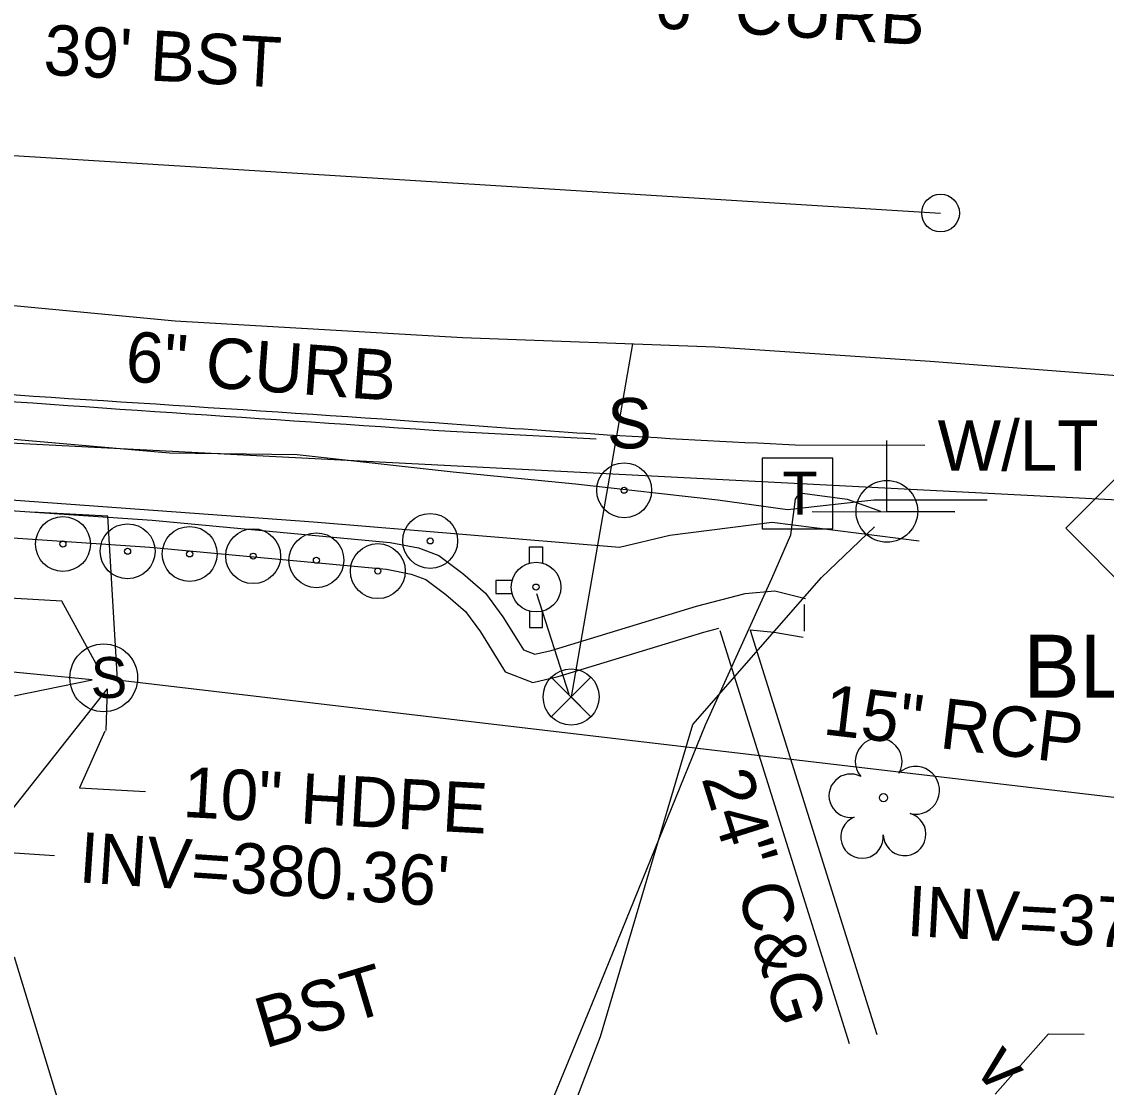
# Model space of a CAD drawing. Extents: x 2089016 to 2094354, y 862840 to 864725.
# Drawn here: x 2092984 to 2093070.2, y 863542.1 to 863626.7 of the extents above; entities that cross this region are included whole.
import ezdxf

# ---------------------------------------------------------------- set-up
doc = ezdxf.new("R2010")
doc.units = 0
for name, color, linetype in [('CTL Supplemental Horizontal and Vertical CELL', 7, 'Continuous'), ('CTL Supplemental Horizontal and Vertical Text', 7, 'Continuous'), ('Exist Building', 7, 'Continuous'), ('Exist Horizontal Alignment', 7, 'Continuous'), ('Exist Horizontal Alignment Station Label', 7, 'Continuous'), ('Exist Other Culture Located Object CELL', 7, 'Continuous'), ('Exist Other Culture Sign Text', 7, 'Continuous'), ('Exist Right of Way Line', 7, 'Continuous'), ('Exist Roads Curbs', 7, 'Continuous'), ('Exist Roads Curbs Text', 7, 'Continuous'), ('Exist Roads EOP', 7, 'Continuous'), ('Exist Roads EOP Other', 7, 'Continuous'), ('Exist Roads EOP Other Text', 7, 'Continuous'), ('Exist Roads EOP Text', 7, 'Continuous'), ('Exist Structure Minor Culvert Topo Terminator', 7, 'Continuous'), ('Exist Structure Minor Paved Ditch or Gutter', 7, 'Continuous'), ('Exist Structure Minor Pipes HDPE 10 Inch', 7, 'Continuous'), ('Exist Structure Minor Pipes HDPE 10 Inch Invert', 7, 'Continuous'), ('Exist Structure Minor Pipes HDPE 10 Inch Leader', 7, 'Continuous'), ('Exist Structure Minor Pipes HDPE 10 Inch Text', 7, 'Continuous'), ('Exist Structure Minor Pipes RCP 15 Inch', 7, 'Continuous'), ('Exist Structure Minor Pipes RCP 15 Inch Invert', 7, 'Continuous'), ('Exist Structure Minor Pipes RCP 15 Inch Leader', 7, 'Continuous'), ('Exist Structure Minor Pipes RCP 15 Inch Text', 7, 'Continuous'), ('Exist Structure Minor Storm Sewer Manhole CELL', 7, 'Continuous'), ('Exist Structure Minor Storm Sewer Manhole Leader', 7, 'Continuous'), ('Exist Utilities Power Joint Use Telephone Text', 7, 'Continuous'), ('Exist Utilities Power UG Cable SUE LOS B', 7, 'Continuous'), ('Exist Utilities Telephone Pedestal CELL', 7, 'Continuous'), ('Exist Utilities Telephone UG Cable SUE LOS B', 7, 'Continuous'), ('Exist Utilities Water UG Line SUE LOS B', 7, 'Continuous'), ('Exist Utilities Water UG Line SUE LOS C', 7, 'Continuous'), ('Exist Vegetation Hedge Row', 7, 'Continuous'), ('Exist Vegetation Tree CELL', 7, 'Continuous'), ('Prop Conc Driveway', 7, 'Continuous'), ('Prop Erosion Embankment Toe Protection with Rip Rap 2 Detail CELL', 7, 'Continuous'), ('Prop Erosion Rip Rap Pad at Outlet Label', 7, 'Continuous'), ('Prop SS Fill Line', 7, 'Continuous'), ('R5707_NCDOT_FS_170814 - Exist Utilities Water UG Line SUE LOS B', 7, 'Continuous')]:
    doc.layers.add(name, color=color, linetype=linetype)

msp = doc.modelspace()

# ---------------------------------------------------------------- linework, layer by layer
at = {"layer": 'CTL Supplemental Horizontal and Vertical CELL'}
msp.add_lwpolyline([(2093067.004, 863586.524), (2093072.246, 863591.765), (2093077.496, 863586.515), (2093072.254, 863581.273)], close=True, dxfattribs=at)
at = {"layer": 'Exist Building'}
for p, q in [((2092978.975, 863589.073), (2093007.222, 863587.021)), ((2093007.222, 863587.021), (2093031.526, 863585.014))]:
    msp.add_line(p, q, dxfattribs=at)
msp.add_lwpolyline([(2092876.627, 863421.444), (2092852.192, 863498.242), (2092850.753, 863503.41), (2092851.048, 863506.429), (2092852.03, 863509.247), (2092853.537, 863511.694), (2092856.63, 863514.147), (2092866.579, 863516.845), (2092929.743, 863535.832), (2092983.435, 863552.499), (2093001.362, 863493.669), (2093002.398, 863490.352), (2093002.956, 863488.108), (2092994.326, 863472.797), (2093011.701, 863463.03), (2093003.046, 863446.38), (2092985.186, 863455.795), (2092876.596, 863421.423)], close=True, dxfattribs=at)
at = {"layer": 'Exist Horizontal Alignment'}
msp.add_line((2092859.181, 863623.858), (2093057.049, 863611.554), dxfattribs=at)
at = {"layer": 'Exist Horizontal Alignment Station Label'}
msp.add_circle((2093057.049, 863611.554), 1.5, dxfattribs=at)
at = {"layer": 'Exist Other Culture Located Object CELL'}
for centre, radius in [((2092987.318, 863585.27), 2.18), ((2092992.454, 863584.695), 2.18), ((2092997.385, 863584.482), 2.18), ((2093002.432, 863584.308), 2.18), ((2093007.458, 863583.983), 2.18), ((2092987.318, 863585.27), 0.24), ((2092992.454, 863584.695), 0.24), ((2093012.336, 863583.119), 2.18), ((2092997.385, 863584.482), 0.24), ((2093002.432, 863584.308), 0.24), ((2093007.458, 863583.983), 0.24), ((2093012.336, 863583.119), 0.24)]:
    msp.add_circle(centre, radius, dxfattribs=at)
at = {"layer": 'Exist Right of Way Line'}
msp.add_line((2092887.594, 863598.226), (2093123.991, 863586.06), dxfattribs=at)
at = {"layer": 'Exist Roads Curbs'}
msp.add_line((2093018.111, 863594.221), (2093029.677, 863593.627), dxfattribs=at)
for points in [[(2092894.675, 863574.886), (2092912.072, 863580.374), (2092930.578, 863586.234), (2092943.261, 863590.055), (2092945.833, 863590.454), (2092965.978, 863589.091), (2092994.403, 863587.166), (2093013.319, 863585.386), (2093015.572, 863584.956), (2093017.173, 863584.359), (2093019.088, 863582.941), (2093020.9, 863581.362), (2093022.271, 863579.494), (2093023.387, 863577.707), (2093023.897, 863576.857), (2093024.803, 863576.51), (2093026.116, 863576.811), (2093037.656, 863580.342), (2093041.515, 863581.328), (2093043.892, 863581.551), (2093046.328, 863580.947)], [(2093046.132, 863577.847), (2093043.825, 863578.232), (2093041.931, 863578.418), (2093045.789, 863566.093), (2093051.996, 863546.313)]]:
    msp.add_lwpolyline(points, dxfattribs=at)
msp.add_spline([(2092836.882, 863591.974), (2092839.402, 863592.978), (2092859.829, 863600.59), (2092883.194, 863603.249), (2092901.658, 863602.034), (2092935.152, 863599.946), (2092973.876, 863597.253), (2093018.111, 863594.221)], degree=3, dxfattribs=at)
at = {"layer": 'Exist Roads EOP'}
msp.add_line((2093045.487, 863593.143), (2093055.8, 863593.112), dxfattribs=at)
msp.add_spline([(2092783.649, 863530.803), (2092785.597, 863535.097), (2092792.694, 863549.723), (2092807.464, 863570.012), (2092820.61, 863582.257), (2092829.779, 863588.664), (2092831.761, 863589.721), (2092836.762, 863592.495), (2092839.093, 863593.515), (2092859.841, 863601.083), (2092883.166, 863603.689), (2092901.828, 863602.719), (2092935.142, 863600.426), (2092973.9, 863597.741), (2093018.255, 863594.812), (2093029.571, 863594.017), (2093045.487, 863593.143)], degree=3, dxfattribs=at)
at = {"layer": 'Exist Roads EOP Other'}
for points in [[(2092895.077, 863572.767), (2092912.717, 863578.332), (2092931.21, 863584.188), (2092943.736, 863587.961), (2092945.927, 863588.301), (2092965.833, 863586.955), (2092994.23, 863585.031), (2093013.018, 863583.263), (2093014.993, 863582.887), (2093016.141, 863582.458), (2093017.745, 863581.271), (2093019.314, 863579.903), (2093020.497, 863578.291), (2093021.56, 863576.588), (2093022.441, 863575.122), (2093024.645, 863574.277), (2093026.669, 863574.741), (2093038.235, 863578.28), (2093039.438, 863578.587)], [(2093039.507, 863578.399), (2093043.577, 863565.399), (2093049.783, 863545.619)]]:
    msp.add_lwpolyline(points, dxfattribs=at)
at = {"layer": 'Exist Structure Minor Paved Ditch or Gutter'}
msp.add_line((2093046.207, 863580.462), (2093046.215, 863578.34), dxfattribs=at)
at = {"layer": 'Exist Structure Minor Pipes HDPE 10 Inch'}
msp.add_line((2092990.823, 863573.765), (2092990.715, 863570.468), dxfattribs=at)
at = {"layer": 'Exist Structure Minor Pipes HDPE 10 Inch Leader'}
for points in [[(2092990.823, 863573.765), (2092980.658, 863560.937), (2092986.645, 863560.54)], [(2092990.644, 863570.398), (2092988.633, 863565.919), (2092993.868, 863565.629)]]:
    msp.add_lwpolyline(points, dxfattribs=at)
at = {"layer": 'Exist Structure Minor Pipes RCP 15 Inch'}
for p, q in [((2092856.706, 863547.53), (2092989.64, 863574.49)), ((2092991.647, 863574.488), (2093086.405, 863563.337))]:
    msp.add_line(p, q, dxfattribs=at)
at = {"layer": 'Exist Structure Minor Pipes RCP 15 Inch Leader'}
for points in [[(2092991.647, 863574.488), (2092990.888, 863587.476), (2092984.842, 863587.81)], [(2092989.64, 863574.49), (2092980.884, 863575.334), (2092974.894, 863575.665)], [(2093061.382, 863541.592), (2093065.634, 863546.385), (2093068.457, 863546.342)]]:
    msp.add_lwpolyline(points, dxfattribs=at)
at = {"layer": 'Exist Structure Minor Storm Sewer Manhole CELL'}
msp.add_circle((2092990.559, 863574.647), 2.694, dxfattribs=at)
at = {"layer": 'Exist Structure Minor Storm Sewer Manhole Leader'}
msp.add_lwpolyline([(2092990.559, 863574.647), (2092987.217, 863580.742), (2092981.226, 863581.073)], dxfattribs=at)
at = {"layer": 'Exist Utilities Power UG Cable SUE LOS B'}
msp.add_lwpolyline([(2093015.514, 863511.335), (2093023.641, 863529.45), (2093030.032, 863546.152), (2093037.352, 863570.951), (2093047.582, 863582.622), (2093051.807, 863586.63)], dxfattribs=at)
at = {"layer": 'Exist Utilities Telephone Pedestal CELL'}
msp.add_line((2093045.606, 863589.315), (2093045.606, 863589.315), dxfattribs=at)
msp.add_lwpolyline([(2093042.882, 863586.489), (2093048.476, 863586.489), (2093048.476, 863592.083), (2093042.882, 863592.083), (2093042.882, 863586.489)], dxfattribs=at)
at = {"layer": 'Exist Utilities Telephone UG Cable SUE LOS B'}
for points in [[(2092779.886, 863512.858), (2092788.107, 863530.526), (2092797.403, 863547.579), (2092809.235, 863563.23), (2092822.643, 863575.422), (2092828.878, 863582.856), (2092836.045, 863587.143), (2092845.526, 863592.531), (2092859.167, 863597.48), (2092876.604, 863599.467), (2092893.555, 863598.148), (2092906.053, 863598.419), (2092920.812, 863597.716), (2092953.006, 863595.424), (2092975.528, 863594.29), (2092995.787, 863592.5), (2093005.921, 863592.377), (2093018.315, 863590.993), (2093028.039, 863590.053), (2093039.357, 863588.772), (2093044.888, 863588.007), (2093051.758, 863588.783), (2093060.741, 863588.782)], [(2093017.627, 863510.668), (2093019.778, 863521.912), (2093021.817, 863530.427), (2093029.382, 863548.842), (2093038.358, 863570.903), (2093043.651, 863582.531), (2093045.157, 863586.005), (2093045.509, 863588.84), (2093045.874, 863589.334), (2093049.616, 863588.824), (2093052.264, 863587.881)]]:
    msp.add_lwpolyline(points, dxfattribs=at)
at = {"layer": 'Exist Utilities Water UG Line SUE LOS B'}
msp.add_line((2093027.541, 863573.326), (2093024.96, 863581.304), dxfattribs=at)
at = {"layer": 'Exist Utilities Water UG Line SUE LOS C'}
msp.add_line((2093032.558, 863601.178), (2093027.696, 863573.123), dxfattribs=at)
at = {"layer": 'Exist Vegetation Hedge Row'}
msp.add_lwpolyline([(2093031.526, 863585.014), (2093035.524, 863585.97), (2093043.662, 863586.997), (2093055.346, 863585.534)], dxfattribs=at)
at = {"layer": 'Exist Vegetation Tree CELL'}
msp.add_line((2093052.514, 863565.124), (2093052.514, 863565.124), dxfattribs=at)
msp.add_circle((2093052.514, 863565.124), 0.326, dxfattribs=at)
for centre, radius, start, end in [((2093052.129, 863567.997), 1.856, 330.16508, 219.71335), ((2093055.063, 863565.713), 1.899, 257.1011, 134.19993), ((2093049.909, 863565.278), 1.727, 62.66361, 279.3457), ((2093050.81, 863562.003), 1.689, 111.56708, 6.23104), ((2093054.187, 863562.224), 1.698, 181.28216, 74.55999)]:
    msp.add_arc(centre, radius, start, end, dxfattribs=at)
at = {"layer": 'Prop Conc Driveway'}
for centre, radius in [((2093031.907, 863589.538), 2.18), ((2093031.907, 863589.538), 0.24), ((2093016.496, 863585.517), 2.18), ((2093016.496, 863585.517), 0.24)]:
    msp.add_circle(centre, radius, dxfattribs=at)
at = {"layer": 'Prop Erosion Embankment Toe Protection with Rip Rap 2 Detail CELL'}
msp.add_lwpolyline([(2093029.271, 863574.698), (2093026.121, 863571.548), (2093027.696, 863573.123), (2093029.271, 863571.548), (2093026.121, 863574.698)], dxfattribs=at)
msp.add_circle((2093027.696, 863573.123), 2.227, dxfattribs=at)
at = {"layer": 'Prop Erosion Rip Rap Pad at Outlet Label'}
msp.add_line((2093024.907, 863581.85), (2093024.907, 863581.85), dxfattribs=at)
for points in [[(2093024.394, 863583.763), (2093024.394, 863585.05), (2093025.419, 863585.05), (2093025.419, 863583.738)], [(2093022.994, 863582.363), (2093021.707, 863582.363), (2093021.707, 863581.338), (2093022.994, 863581.338)], [(2093024.394, 863579.938), (2093024.394, 863578.65), (2093025.419, 863578.65), (2093025.419, 863579.963)]]:
    msp.add_lwpolyline(points, dxfattribs=at)
for radius in [1.977, 0.243]:
    msp.add_circle((2093024.907, 863581.85), radius, dxfattribs=at)
at = {"layer": 'Prop SS Fill Line'}
msp.add_line((2093052.777, 863587.86), (2093052.777, 863587.86), dxfattribs=at)
msp.add_lwpolyline([(2093046.839, 863587.86), (2093058.177, 863587.823), (2093052.777, 863587.84), (2093052.777, 863593.485)], dxfattribs=at)
msp.add_circle((2093052.778, 863587.866), 2.45, dxfattribs=at)
at = {"layer": 'R5707_NCDOT_FS_170814 - Exist Utilities Water UG Line SUE LOS B'}
msp.add_lwpolyline([(2092619.751, 863665.407), (2092671.678, 863651.842), (2092719.092, 863639.535), (2092772.31, 863627.101), (2092789.8, 863623.16), (2092809.471, 863618.359), (2092826.855, 863614.852), (2092866.665, 863612.165), (2092893.616, 863610.376), (2092921.684, 863608.509), (2092953.831, 863606.191), (2092976.13, 863604.887), (2092996.225, 863602.986), (2093019.054, 863601.683), (2093039.123, 863600.932), (2093056.228, 863599.794), (2093073.143, 863598.504)], dxfattribs=at)

# ---------------------------------------------------------------- texts
at = {"layer": 'CTL Supplemental Horizontal and Vertical Text'}
msp.add_text('BL-10', height=5, dxfattribs=at).set_placement((2093063.637, 863573.07))
at = {"layer": 'Exist Other Culture Sign Text'}
msp.add_text('S', height=4, dxfattribs=at).set_placement((2093030.543, 863592.864))
at = {"layer": 'Exist Roads Curbs Text'}
for s, rotation, p in [('6" CURB', 356.27502, (2093034.225, 863626.26)), ('6" CURB', 355.79502, (2092992.2, 863598.202)), ('24" C&G', 287.42022, (2093038.031, 863566.671))]:
    msp.add_text(s, height=4, rotation=rotation, dxfattribs=at).set_placement(p)
at = {"layer": 'Exist Roads EOP Other Text'}
msp.add_text('BST', height=4, rotation=16.65485, dxfattribs=at).set_placement((2093003.356, 863545.195))
at = {"layer": 'Exist Roads EOP Text'}
msp.add_text("NC 56/50    E WILTON AVE   39' BST", height=4, rotation=356.86028, dxfattribs=at).set_placement((2092914.78, 863626.437))
at = {"layer": 'Exist Structure Minor Culvert Topo Terminator'}
msp.add_text('v', height=3.968, rotation=310.53652, dxfattribs=at).set_placement((2093059.649, 863543.516))
at = {"layer": 'Exist Structure Minor Pipes HDPE 10 Inch Invert'}
msp.add_text("INV=380.36'", height=4, rotation=356.20203, dxfattribs=at).set_placement((2092988.508, 863558.412))
at = {"layer": 'Exist Structure Minor Pipes HDPE 10 Inch Text'}
msp.add_text('10" HDPE', height=4, rotation=356.83624, dxfattribs=at).set_placement((2092996.78, 863563.603))
at = {"layer": 'Exist Structure Minor Pipes RCP 15 Inch Invert'}
msp.add_text("INV=378.30'", height=4, rotation=356.83624, dxfattribs=at).set_placement((2093054.284, 863554.164))
at = {"layer": 'Exist Structure Minor Pipes RCP 15 Inch Text'}
msp.add_text('15" RCP', height=4, rotation=353.28852, dxfattribs=at).set_placement((2093047.618, 863570.168))
at = {"layer": 'Exist Structure Minor Storm Sewer Manhole CELL'}
msp.add_text('S', height=3.25, dxfattribs=at).set_placement((2092989.528, 863573.047))
at = {"layer": 'Exist Utilities Power Joint Use Telephone Text'}
msp.add_text('W/LT', height=4, dxfattribs=at).set_placement((2093056.812, 863591.098))
at = {"layer": 'Exist Utilities Telephone Pedestal CELL'}
msp.add_text('T', height=3.42, dxfattribs=at).set_placement((2093044.475, 863587.601))

doc.saveas('drawing.dxf')
